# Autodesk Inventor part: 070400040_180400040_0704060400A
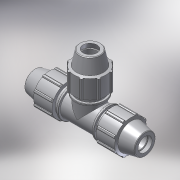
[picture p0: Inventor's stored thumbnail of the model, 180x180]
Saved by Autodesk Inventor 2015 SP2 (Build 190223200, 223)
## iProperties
Created: 2017-02
Part Number: 070400040_180400040_0704060400A
Material: PVC-Piping
Description: PLASSON TEE 40-40-40
Document SubType Name: Modeling
Designer: KIM
Mass: 92.6774 g
Surface Area: 199.44 cm^2
Volume: 66.1981 cm^3
Density: 1.4 g/cm^3
Appearance: Smooth - White
Author: KIM
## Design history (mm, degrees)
derived "07040.ipt"
feature "Solid1::07040.ipt"
tag "TaggingFeature1"
body "Solid1"
other parameters: "d4" = 9.25, "d5" = 27.75, "d7" = 82, "d11" = 3.7, "d13" = 120 deg, "d15" = 12 deg, "d16" = 71.34, "d18" = 2, "d19" = 35 deg, "d20" = 17.5 deg, "d21" = 76.26, "d23" = 0, "d25" = 360 deg, "d27" = 1.64, "d33" = 0.8, "d42" = 38.85, "d43" = 2.46, "d46" = 1.2, "d63" = 86, "d67" = 61.5, "d77" = 82, "d78" = 12 deg, "d79" = 111, "d80" = 120 deg, "d82" = 9.25, "d85" = 61.5, "d86" = 71.34, "d87" = 3.7, "d88" = 3.7, "d89" = 27.75, "d90" = 38.85, "d96" = 11.1, "d98" = 76.26, "d99" = 35 deg, "d100" = 17.5 deg, "d102" = 0, "d103" = 1.64, "d107" = 360 deg, "d109" = 1.2, "d112" = 2, "d118" = 360 deg, "d121" = 0, "d128" = 221, "d131" = 36, "d132" = 36, "d133" = 86, "d134" = 1.72, "d135" = 11.1, "d152" = 0, "d154" = 0, "d156" = 0, "d158" = 0, "E_" = 82, "A_" = 111, "l_" = 86, "H_" = 221
